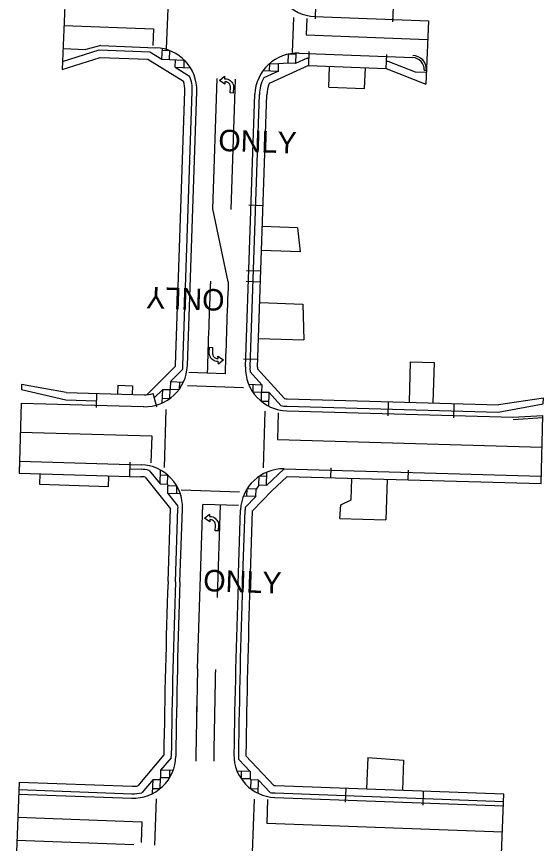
# Model space of a CAD drawing. Extents: x 979036 to 996074, y 1836928 to 1845163.
# Drawn here: x 992347 to 992700, y 1842602 to 1843157 of the extents above; entities that cross this region are included whole.
import ezdxf

# ---------------------------------------------------------------- set-up
doc = ezdxf.new("R2010")
doc.units = 0
for name, color, linetype in [('Driveways', 7, 'Continuous'), ('R_Proposed Road', 7, 'Continuous'), ('STRIPE_White Crosswalk', 7, 'Continuous'), ('STRIPE_White Stopbar', 7, 'Continuous'), ('STRIPE_White Turn Arrow', 7, 'Continuous'), ('STRIPE_White_6in', 7, 'Continuous'), ('STRIPE_White_ONLY', 7, 'Continuous'), ('STRIPE_Yellow Dbl 6in', 7, 'Continuous'), ('STRIPE_Yellow_10_30 SKIP', 7, 'Continuous')]:
    doc.layers.add(name, color=color, linetype=linetype)

msp = doc.modelspace()

# ---------------------------------------------------------------- linework, layer by layer
at = {"layer": 'Driveways'}
for p, q in [((992582.47, 1842660.03), (992581.7, 1842638.98)), ((992582.47, 1842660.03), (992606.41, 1842658.17)), ((992606.41, 1842658.17), (992605.68, 1842638.1)), ((992567.7, 1842639.49), (992567.36, 1842630)), ((992619.67, 1842637.59), (992619.32, 1842628.1))]:
    msp.add_line(p, q, dxfattribs=at)
at = {"layer": 'R_Proposed Road'}
for p, q in [((992379.76, 1843176.2), (992377.63, 1843121.23)), ((992547.44, 1843164.74), (992547.07, 1843155.25)), ((992599.4, 1843162.73), (992599.03, 1843153.24)), ((992547.01, 1843156.75), (992623.07, 1843153.81)), ((992623.07, 1843153.81), (992621.44, 1843111.51)), ((992377.84, 1843126.55), (992402.28, 1843134.32)), ((992378.17, 1843135.25), (992393.38, 1843134.67)), ((992403.49, 1843137.28), (992393.38, 1843134.67)), ((992402.28, 1843134.32), (992436.42, 1843133)), ((992403.49, 1843137.28), (992440.42, 1843135.85)), ((992444.48, 1843128.11), (992444.76, 1843135.35)), ((992444.71, 1843134.11), (992449.71, 1843133.91)), ((992449.47, 1843127.92), (992449.71, 1843133.91)), ((992542.86, 1843123.88), (992543.22, 1843133.38)), ((992377.63, 1843121.23), (992402.96, 1843129.29)), ((992402.96, 1843129.29), (992434.93, 1843128.06)), ((992434.93, 1843128.06), (992458.88, 1843113.52)), ((992436.42, 1843133), (992444.48, 1843128.11)), ((992444.48, 1843128.11), (992449.47, 1843127.92)), ((992449.47, 1843127.92), (992459.47, 1843127.53)), ((992529.14, 1843131.5), (992528.91, 1843125.51)), ((992534.11, 1843131.31), (992529.14, 1843131.5)), ((992534.17, 1843132.14), (992533.91, 1843125.31)), ((992541.79, 1843128.93), (992533.91, 1843125.31)), ((992536.35, 1843132.14), (992612.61, 1843129.19)), ((992541.79, 1843128.93), (992543.05, 1843128.88)), ((992594.82, 1843121.88), (992595.18, 1843131.37)), ((992453.28, 1843122.77), (992453.47, 1843127.76)), ((992453.28, 1843122.77), (992463.56, 1843122.37)), ((992453.28, 1843122.77), (992462.98, 1843116.87)), ((992459.27, 1843122.53), (992459.47, 1843127.53)), ((992542.79, 1843123.89), (992516.43, 1843111.79)), ((992516.53, 1843120.32), (992516.72, 1843125.32)), ((992516.72, 1843125.32), (992522.71, 1843125.09)), ((992522.52, 1843120.09), (992522.71, 1843125.09)), ((992528.91, 1843125.51), (992522.71, 1843125.09)), ((992533.88, 1843125.31), (992528.91, 1843125.51)), ((992542.79, 1843123.89), (992594.82, 1843121.88)), ((992556.31, 1843109.35), (992556.85, 1843123.34)), ((992580.29, 1843108.43), (992580.83, 1843122.42)), ((992595.01, 1843126.87), (992595.85, 1843126.84)), ((992595.85, 1843126.84), (992614.26, 1843119.67)), ((992512.24, 1843120.49), (992522.52, 1843120.09)), ((992522.52, 1843120.09), (992512.71, 1843115.59)), ((992594.82, 1843121.88), (992621.44, 1843111.51)), ((992614.26, 1843119.67), (992621.74, 1843119.45)), ((992620.3, 1843120.89), (992621.8, 1843120.83)), ((992453.51, 1842923), (992459.81, 1843106.67)), ((992458.51, 1842922.83), (992464.8, 1843106.5)), ((992461.51, 1842922.73), (992467.8, 1843106.4)), ((992556.31, 1843109.35), (992580.29, 1843108.43)), ((992500.5, 1842921.95), (992506.77, 1843104.64)), ((992503.5, 1842921.85), (992509.76, 1843104.54)), ((992508.5, 1842921.67), (992514.76, 1843104.37)), ((992512.21, 1843029.96), (992502.72, 1843030.29)), ((992535.26, 1843015.16), (992511.73, 1843015.97)), ((992535.26, 1843015.16), (992537.1, 1842999.09)), ((992537.1, 1842999.09), (992511.18, 1842999.98)), ((992510.7, 1842985.99), (992501.21, 1842986.31)), ((992500.97, 1842979.32), (992510.46, 1842978.99)), ((992509.98, 1842965), (992538.95, 1842964.01)), ((992538.95, 1842964.01), (992539.58, 1842939.97)), ((992509.16, 1842941.02), (992539.58, 1842939.97)), ((992499.19, 1842927.35), (992508.68, 1842927.02)), ((992610.88, 1842925.29), (992610.11, 1842898.15)), ((992610.88, 1842925.29), (992626.88, 1842924.84)), ((992626.88, 1842924.84), (992626.1, 1842897.7)), ((992453.48, 1842922.46), (992434.39, 1842903.25)), ((992458.28, 1842920.2), (992450.16, 1842912.02)), ((992503.6, 1842918.55), (992511.46, 1842909.92)), ((992508.49, 1842920.61), (992526.72, 1842900.6)), ((992450.16, 1842912.02), (992449.98, 1842907.02)), ((992450.16, 1842912.02), (992458.88, 1842911.72)), ((992456.15, 1842911.81), (992455.98, 1842906.82)), ((992350.35, 1842910.08), (992350.25, 1842906.62)), ((992350.25, 1842906.62), (992380.06, 1842899.7)), ((992380.2, 1842904.7), (992350.35, 1842910.08)), ((992414.79, 1842909.56), (992414.62, 1842903.72)), ((992414.79, 1842909.56), (992424.78, 1842909.28)), ((992424.78, 1842909.28), (992424.61, 1842903.43)), ((992444.98, 1842906.81), (992439.33, 1842901.13)), ((992444.72, 1842897.71), (992444.98, 1842906.81)), ((992444.98, 1842906.81), (992449.97, 1842906.67)), ((992449.8, 1842900.67), (992449.98, 1842907.02)), ((992449.98, 1842907.02), (992455.98, 1842906.82)), ((992502.59, 1842910.22), (992511.46, 1842909.92)), ((992505.47, 1842910.12), (992505.3, 1842905.13)), ((992511.46, 1842909.92), (992511.29, 1842904.92)), ((992380.2, 1842904.7), (992432.44, 1842903.21)), ((992400.62, 1842904.12), (992400.35, 1842894.62)), ((992441.1, 1842894.81), (992438.54, 1842903.96)), ((992444.81, 1842900.81), (992449.8, 1842900.67)), ((992505.3, 1842905.13), (992511.29, 1842904.92)), ((992511.12, 1842898.77), (992511.29, 1842904.92)), ((992516.29, 1842904.62), (992511.29, 1842904.77)), ((992516.03, 1842895.59), (992516.29, 1842904.62)), ((992516.03, 1842895.59), (992516.29, 1842904.62)), ((992516.29, 1842904.62), (992524.21, 1842895.92)), ((992700.23, 1842900.88), (992670.09, 1842896.45)), ((992700.12, 1842897.19), (992700.23, 1842900.88)), ((992349.99, 1842897.56), (992348.65, 1842850.57)), ((992349.99, 1842897.56), (992432.21, 1842895.22)), ((992380.06, 1842899.7), (992400.48, 1842899.12)), ((992516.11, 1842898.63), (992511.12, 1842898.77)), ((992528.26, 1842895.48), (992669.94, 1842891.45)), ((992528.4, 1842900.48), (992670.09, 1842896.45)), ((992596.12, 1842898.55), (992595.85, 1842889.06)), ((992640.1, 1842897.3), (992639.83, 1842887.8)), ((992669.94, 1842891.45), (992700.12, 1842897.19)), ((992528.17, 1842892.48), (992679.86, 1842888.17)), ((992679.72, 1842888.16), (992699.9, 1842889.37)), ((992679.81, 1842886.67), (992699.85, 1842887.86)), ((992698.6, 1842843.61), (992699.9, 1842889.37)), ((992348.88, 1842858.57), (992430.54, 1842856.25)), ((992348.91, 1842850.57), (992349.18, 1842860.06)), ((992422.88, 1842848.46), (992423.15, 1842857.96)), ((992423.02, 1842853.46), (992430.46, 1842853.25)), ((992435.95, 1842852.49), (992443.17, 1842843.49)), ((992443.17, 1842843.49), (992443.44, 1842852.75)), ((992526.51, 1842853.51), (992514.52, 1842842.47)), ((992514.52, 1842842.47), (992514.77, 1842851.35)), ((992526.51, 1842853.51), (992698.74, 1842848.61)), ((992557.65, 1842847.63), (992557.84, 1842854.12)), ((992609.63, 1842846.15), (992609.82, 1842852.64)), ((992348.65, 1842850.57), (992430.32, 1842848.25)), ((992362.7, 1842842.98), (992362.9, 1842850.17)), ((992408.67, 1842841.4), (992408.89, 1842848.86)), ((992433.17, 1842847.97), (992450.21, 1842826.73)), ((992443.34, 1842849.49), (992448.34, 1842849.34)), ((992448.17, 1842843.35), (992448.34, 1842849.34)), ((992509.52, 1842842.61), (992509.69, 1842848.61)), ((992514.69, 1842848.47), (992509.69, 1842848.61)), ((992528.4, 1842848.46), (992518.02, 1842838.9)), ((992528.4, 1842848.46), (992698.6, 1842843.61)), ((992571.23, 1842832.71), (992571.65, 1842847.23)), ((992594.86, 1842819.38), (992595.64, 1842846.55)), ((992408.67, 1842841.4), (992362.7, 1842842.98)), ((992443.17, 1842843.49), (992448.17, 1842843.35)), ((992448.17, 1842843.35), (992448.52, 1842842.04)), ((992448.35, 1842837.04), (992448.52, 1842842.04)), ((992454.52, 1842841.83), (992448.52, 1842842.04)), ((992454.34, 1842836.83), (992454.52, 1842841.83)), ((992501.41, 1842835.22), (992501.58, 1842840.22)), ((992507.58, 1842840.01), (992501.58, 1842840.22)), ((992507.4, 1842835.01), (992507.58, 1842840.01)), ((992509.52, 1842842.61), (992507.58, 1842840.01)), ((992514.52, 1842842.47), (992509.52, 1842842.61)), ((992456.78, 1842836.75), (992448.35, 1842837.04)), ((992448.35, 1842837.04), (992455.22, 1842828.47)), ((992507.4, 1842835.01), (992499.11, 1842835.3)), ((992507.4, 1842835.01), (992500.32, 1842827.59)), ((992518.02, 1842838.9), (992505.2, 1842825.46)), ((992563.81, 1842820.27), (992564.41, 1842829.31)), ((992564.41, 1842829.31), (992571.23, 1842832.71)), ((992448.54, 1842777.98), (992450.21, 1842826.73)), ((992453.53, 1842777.81), (992455.22, 1842826.88)), ((992456.53, 1842777.71), (992458.22, 1842826.78)), ((992495.51, 1842776.37), (992497.21, 1842826)), ((992498.51, 1842776.27), (992500.21, 1842825.9)), ((992503.5, 1842776.1), (992505.2, 1842825.46)), ((992563.81, 1842820.27), (992594.54, 1842819.39)), ((992445.73, 1842661.75), (992428.28, 1842640.95)), ((992450.68, 1842659.88), (992443.59, 1842651.43)), ((992495.88, 1842658.96), (992503.64, 1842650.74)), ((992500.74, 1842661.09), (992519.44, 1842641.29)), ((992443.59, 1842651.43), (992443.53, 1842646.43)), ((992451.95, 1842651.33), (992443.59, 1842651.43)), ((992449.59, 1842651.36), (992449.53, 1842646.36)), ((992443.27, 1842639.17), (992443.53, 1842646.43)), ((992449.53, 1842646.36), (992443.53, 1842646.43)), ((992503.64, 1842650.74), (992494.89, 1842650.84)), ((992497.64, 1842650.81), (992497.58, 1842645.81)), ((992503.58, 1842645.74), (992497.58, 1842645.81)), ((992503.64, 1842650.74), (992503.58, 1842645.74)), ((992503.58, 1842645.74), (992504.25, 1842644.98)), ((992348.71, 1842643.51), (992346.98, 1842596.54)), ((992348.71, 1842643.51), (992424.47, 1842640.74)), ((992438.49, 1842645.35), (992430.97, 1842636.38)), ((992438.14, 1842635.82), (992438.49, 1842645.35)), ((992438.49, 1842645.35), (992443.49, 1842645.17)), ((992504.03, 1842638.99), (992504.25, 1842644.98)), ((992509.24, 1842644.8), (992504.25, 1842644.98)), ((992508.92, 1842636.01), (992509.24, 1842644.8)), ((992509.24, 1842644.8), (992517.03, 1842636.56)), ((992520.48, 1842641.22), (992673.63, 1842635.61)), ((992348.41, 1842635.52), (992424.17, 1842632.74)), ((992348.52, 1842638.52), (992424.28, 1842635.74)), ((992438.27, 1842639.35), (992443.27, 1842639.17)), ((992509.03, 1842638.81), (992504.03, 1842638.99)), ((992520.3, 1842636.23), (992673.45, 1842630.62)), ((992671.75, 1842584.2), (992673.63, 1842635.61)), ((992520.19, 1842633.23), (992673.34, 1842627.62)), ((992347.28, 1842604.54), (992425.7, 1842601.67))]:
    msp.add_line(p, q, dxfattribs=at)
for centre, radius, start, end in [((992548.11, 1843185.23), 28.5, 173.8765, 267.7861), ((992439.32, 1843107.37), 28.5, 358.0361, 87.7861), ((992535.25, 1843103.66), 28.5, 87.7861, 178.0361), ((992612.3, 1843121.2), 8, 357.7861, 87.7861), ((992612.3, 1843121.2), 9.5, 357.7861, 87.7861), ((992439.32, 1843107.37), 25.5, 358.0361, 21.8732), ((992439.32, 1843107.37), 20.5, 358.0361, 17.4406), ((992535.25, 1843103.66), 25.5, 152.123, 178.0361), ((992535.25, 1843103.66), 20.5, 156.6364, 178.0361), ((992433.02, 1842923.7), 28.5, 268.3694, 358.0361), ((992433.02, 1842923.7), 20.5, 356.5314, 358.0361), ((992433.02, 1842923.7), 25.5, 352.092, 358.0361), ((992528.98, 1842920.97), 28.5, 178.0361, 268.3694), ((992528.98, 1842920.97), 25.5, 178.0361, 185.4472), ((992528.98, 1842920.97), 20.5, 178.0361, 181.0117), ((992433.02, 1842923.7), 20.5, 268.3694, 285.6222), ((992528.98, 1842920.97), 20.5, 263.6457, 268.3694), ((992528.98, 1842920.97), 25.5, 259.2102, 268.3694), ((992429.73, 1842827.76), 28.5, 358.0361, 88.3694), ((992429.73, 1842827.76), 25.5, 75.8794, 88.3694), ((992525.69, 1842825.03), 28.5, 88.3694, 178.0361), ((992429.73, 1842827.76), 20.5, 80.3487, 88.3694), ((992429.73, 1842827.76), 25.5, 358.0361, 1.6001), ((992525.69, 1842825.03), 25.5, 174.2294, 178.0361), ((998202.23, 1842580.69), 5757.08, 178.036106, 179.193225), ((998202.23, 1842580.69), 5752.08, 178.036106, 179.201336), ((998202.23, 1842580.69), 5749.08, 178.036106, 179.201336), ((998202.23, 1842580.69), 5710.08, 178.03611, 179.18294), ((998202.23, 1842580.69), 5707.08, 178.03611, 179.18294), ((998202.23, 1842580.69), 5702.08, 178.03611, 179.18294), ((992425.22, 1842661.22), 28.5, 267.9024, 359.2013), ((992425.22, 1842661.22), 25.5, 356.9794, 359.2013), ((992521.23, 1842661.71), 28.5, 179.1829, 267.9024), ((992521.23, 1842661.71), 25.5, 179.1829, 186.1988), ((992521.23, 1842661.71), 25.5, 179.1829, 186.1988), ((992521.23, 1842661.71), 20.5, 179.1829, 181.7279), ((992425.22, 1842661.22), 20.5, 267.9024, 278.5888), ((992521.23, 1842661.71), 20.5, 264.974, 267.9024), ((992425.22, 1842661.22), 25.5, 267.9024, 283.0361), ((992521.23, 1842661.71), 25.5, 260.5031, 267.9024)]:
    msp.add_arc(centre, radius, start, end, dxfattribs=at)
at = {"layer": 'STRIPE_White Crosswalk'}
for p, q in [((992448.3, 1843162.21), (992447.25, 1843135.19)), ((992532.59, 1843156.12), (992531.68, 1843132.53)), ((992499.08, 1842907.84), (992461.56, 1842909.13)), ((992447.09, 1842893.35), (992445.99, 1842854.45)), ((992513.43, 1842892.29), (992512.35, 1842854.19)), ((992496.51, 1842837.89), (992457.45, 1842839.23)), ((992440.52, 1842632.3), (992439.38, 1842601.28)), ((992506.28, 1842632.1), (992504.97, 1842596.34))]:
    msp.add_line(p, q, dxfattribs=at)
at = {"layer": 'STRIPE_White Stopbar'}
for p, q in [((992541.58, 1843155.46), (992541.15, 1843144.47)), ((992438.76, 1843148.42), (992438.33, 1843137.43)), ((992486.83, 1842917.27), (992462.49, 1842918.1)), ((992522.4, 1842891.15), (992521.89, 1842873.15)), ((992437.58, 1842875.55), (992437.07, 1842857.56)), ((992495.81, 1842828.91), (992471.82, 1842829.73)), ((992515.28, 1842631.91), (992514.69, 1842615.92)), ((992430.95, 1842616.98), (992430.44, 1842602.99))]:
    msp.add_line(p, q, dxfattribs=at)
at = {"layer": 'STRIPE_White Turn Arrow'}
for points in [[(992486.69, 1843111.42), (992483.1, 1843113.89), (992486.41, 1843116.74), (992486.5, 1843115.07), (992487.16, 1843115.05), (992487.74, 1843114.99), (992488.53, 1843114.79), (992489.45, 1843114.38), (992490.17, 1843113.94), (992490.74, 1843113.36), (992491.4, 1843112.7), (992491.77, 1843112), (992492.17, 1843111.24), (992492.4, 1843110.29), (992492.51, 1843109.3), (992492.28, 1843105.4), (992490.28, 1843105.51), (992490.46, 1843109.1), (992490.44, 1843109.8), (992490.25, 1843110.54), (992489.91, 1843111.33), (992489.36, 1843112), (992489.07, 1843112.23), (992488.47, 1843112.63), (992487.72, 1843112.91), (992486.99, 1843113.05), (992486.6, 1843113.08)], [(992482.03, 1842929.07), (992485.62, 1842926.59), (992482.31, 1842923.75), (992482.22, 1842925.41), (992481.56, 1842925.43), (992480.98, 1842925.5), (992480.19, 1842925.7), (992479.27, 1842926.1), (992478.55, 1842926.55), (992477.98, 1842927.12), (992477.32, 1842927.78), (992476.95, 1842928.48), (992476.55, 1842929.25), (992476.32, 1842930.2), (992476.21, 1842931.18), (992476.44, 1842935.08), (992478.44, 1842934.97), (992478.26, 1842931.38), (992478.28, 1842930.69), (992478.47, 1842929.94), (992478.81, 1842929.15), (992479.36, 1842928.48), (992479.65, 1842928.25), (992480.25, 1842927.85), (992481, 1842927.57), (992481.73, 1842927.43), (992482.12, 1842927.4)], [(992476.63, 1842817.93), (992473.03, 1842820.41), (992476.35, 1842823.25), (992476.43, 1842821.59), (992477.1, 1842821.56), (992477.67, 1842821.5), (992478.47, 1842821.3), (992479.39, 1842820.89), (992480.1, 1842820.45), (992480.67, 1842819.87), (992481.34, 1842819.21), (992481.71, 1842818.51), (992482.11, 1842817.75), (992482.33, 1842816.8), (992482.44, 1842815.81), (992482.21, 1842811.91), (992480.21, 1842812.03), (992480.39, 1842815.62), (992480.37, 1842816.31), (992480.18, 1842817.05), (992479.84, 1842817.85), (992479.3, 1842818.51), (992479.01, 1842818.74), (992478.41, 1842819.14), (992477.66, 1842819.42), (992476.93, 1842819.57), (992476.54, 1842819.59)]]:
    msp.add_lwpolyline(points, close=True, dxfattribs=at)
at = {"layer": 'STRIPE_White_6in'}
for p, q in [((992493.55, 1843114.75), (992490.56, 1843027.34)), ((992481.69, 1842767.2), (992483.82, 1842829.32))]:
    msp.add_line(p, q, dxfattribs=at)
msp.add_arc((998208.02, 1842751.91), 5735.58, 177.727775, 178.344751, dxfattribs=at)
at = {"layer": 'STRIPE_Yellow Dbl 6in'}
for p, q in [((992378.77, 1843150.74), (992438.76, 1843148.42)), ((992541.15, 1843144.47), (992622.59, 1843141.32)), ((992478.56, 1843027.71), (992481.56, 1843115.22)), ((992488.94, 1842978.84), (992478.55, 1843027.79)), ((992349.43, 1842878.06), (992437.58, 1842875.55)), ((992521.89, 1842873.15), (992699.29, 1842868.1)), ((992468.33, 1842719.41), (992471.82, 1842829.73)), ((992347.84, 1842620.03), (992430.95, 1842616.98)), ((992514.69, 1842615.92), (992672.7, 1842610.13))]:
    msp.add_line(p, q, dxfattribs=at)
msp.add_arc((998208.02, 1842751.91), 5723.58, 177.72778, 178.34451, dxfattribs=at)
at = {"layer": 'STRIPE_Yellow_10_30 SKIP'}
for centre, radius, start, end in [((998202.23, 1842580.69), 5735.58, 178.614124, 179.231099), ((998202.24, 1842580.69), 5735.58, 178.614124, 179.231099), ((998202.23, 1842580.69), 5723.58, 178.61412, 179.23086), ((998202.24, 1842580.69), 5723.58, 178.61412, 179.23086)]:
    msp.add_arc(centre, radius, start, end, dxfattribs=at)

# ---------------------------------------------------------------- texts
at = {"layer": 'STRIPE_White_ONLY'}
for rotation, p in [(358.0361, (992482.07, 1843066.68)), (178.0361, (992486.65, 1842973.8)), (358.061, (992471.96, 1842771.59))]:
    msp.add_text('ONLY', height=14.4, rotation=rotation, dxfattribs=at).set_placement(p)

doc.saveas('drawing.dxf')
